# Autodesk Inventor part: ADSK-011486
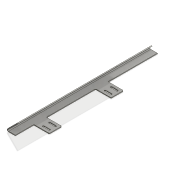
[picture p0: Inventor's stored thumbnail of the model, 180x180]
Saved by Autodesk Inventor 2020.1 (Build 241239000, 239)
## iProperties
Created: 2000-01
Part Number: ADSK-011486
Material: 1.0312 DC05
Description: FSHTPH,SS,CP,01,038,019,230,135,PLOW,END_TAB
Document SubType Name: Tôlerie
Designer: sspink
Density: 1 g/cm^3
Sheet Metal Rule: Stahlblech 1.0312 - DC05 -   3.0 mm
Appearance: Stahl
Mass: 159.325 g
Surface Area: 1118.46 cm^2
Volume: 159.325 cm^3
Flat Pattern Width: 58.4 cm
Flat Pattern Length: 15.7693 cm
Flat Pattern Area: 920.93 cm^2
Sheet Metal Width: 584,000 mm
Sheet Metal Length: 157,693 mm
Sheet Metal Area: 92092,992 mm^2
Control State: 0
Master: False
Checked Out: False
Shininess: 57.0
Length Units: 11269
Angle Units: 11279
Time Units: 11290
Mass Units: 11283
Length Display Precision: 3
Angle Display Precision: 2
Compacted: True
CUTLENGTH: 6.20 X 23.00 (143 SI)
MATERIAL DESC: SHEET,S/S, 11 GA
MATERIAL_NUMBER: A084638
G_L: 157,7x584 mm
Thickness: 3,000 mm
Dimensions: 97,3x50x584 mm
Mass: 0,159 kg
Semi finished: Stahlblech 1.0312 - DC05 -   3.0 mm
DocNumber: ADSK-011486.ipt
Folder: 01 - Themengebiete\Simplification\01 - Packaging machine\
VDS_Category: 3D Komponenten
Density: 8.03
Volumn: 167.52272109722534
Area: 1115.3407113282015
PropertySet Name: Model Information
Author: sspink
Revision Number: -
Title: FSHTPH,SS,CP,01,038,019,230,135,PLOW,END_TAB
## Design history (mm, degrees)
node "Solide1"
  node "Extrusion1" dims "d2" = 406, "d3" = 0
  node "Extrusion2" dims "d7" = 406 (= d2), "d8" = 0
  node "Fillet1" dims "d9" = 3 (= BendRadius)
  node "Fillet2" dims "d10" = 6 (= BendRadius + Thickness)
  node "Extrusion3" dims "d15" = 63.5, "d16" = 0
  node "Extrusion4" dims "d23" = 50.8, "d24" = 0
  node "Fillet3" dims "d25" = 3
  node "Extrusion6" dims "d32" = 178, "d33" = 0
sketch "Sketch1"
  geometry: L1 (0, 0)-(35, 0); L2 (35, 0)-(35, 3); L3 (35, 3)-(0, 3); L4 (0, 3)-(0, 0)
  constraints: 8 end point, 2 parallel, 1 horizontal, 1 perpendicular
  dimensions: "d0" = 3 distance between parallel lines of L1 L3 (= thickness); "d1" = 35 distance between parallel lines of L2 L4
sketch "Sketch2"
  geometry: L1 (0, 0)-(0, 3) reference; L2 (0, 3)-(35, 3) reference; L3 (0, 3)-(44.901, 47.901); L4 (44.901, 47.901)-(42.78, 50.023); L5 (42.78, 50.023)-(-7.243, 0); L6 (-7.243, 0)-(0, 0)
  constraints: 8 end point, 2 parallel, 1 perpendicular
  dimensions: "d4" = 3 distance of L3.end L4.end (= thickness); "d5" = 45 deg angle of L2 L3; "d6" = 63.5 distance of L1.end L3.end
workplane "Arbeitsebene4"
workplane "Arbeitsebene5"
workplane "Arbeitsebene6"
workplane "Arbeitsebene7"
node "FlatPattern"
sketch "Sketch3"
  geometry: L1 (0, 3)-(0, 0) reference; L2 (406, 0)-(0, 0) reference; L3 (406, 0)-(406, 3) reference; L4 (406, 3)-(0, 3) reference; L5 (76, 3)-(76, 0); L6 (127, 3)-(127, 0); L7 (330, 3)-(330, 0); L8 (381, 3)-(381, 0)
  constraints: 8 end point, 8 point on line, 3 parallel, 1 perpendicular
  dimensions: "d11" = 25 distance between parallel lines of L8 L3; "d12" = 76 distance between parallel lines of L7 L3 (= d14); "d13" = 127 distance between parallel lines of L6 L1; "d14" = 76 distance between parallel lines of L5 L1
sketch "Sketch4"
  geometry: L1 (91.257, -330)-(91.257, -279) reference; L2 (91.257, -76)-(91.257, -25) reference; L3 (53.757, -292)-(78.757, -292); L4 (53.757, -295)-(78.757, -295); L5 (78.757, -289)-(53.757, -289); L6 (78.757, -314)-(53.757, -314); L7 (53.757, -317)-(78.757, -317); L8 (53.757, -320)-(78.757, -320); L9 (66.257, -317)-(66.257, -292); L10 (78.757, -35)-(53.757, -35); L11 (53.757, -41)-(78.757, -41); L12 (53.757, -38)-(78.757, -38); L13 (78.757, -60)-(53.757, -60); L14 (53.757, -63)-(78.757, -63); L15 (53.757, -66)-(78.757, -66); L16 (66.257, -63)-(66.257, -38); A1 r 3 centre (53.757, -292) between (53.757, -289) and (53.757, -295); A2 r 3 centre (78.757, -292) between (78.757, -295) and (78.757, -289); A3 r 3 centre (53.757, -317) between (53.757, -314) and (53.757, -320); A4 r 3 centre (78.757, -317) between (78.757, -320) and (78.757, -314); A5 r 3 centre (78.757, -38) between (78.757, -41) and (78.757, -35); A6 r 3 centre (53.757, -38) between (53.757, -35) and (53.757, -41); A7 r 3 centre (53.757, -63) between (53.757, -60) and (53.757, -66); A8 r 3 centre (78.757, -63) between (78.757, -66) and (78.757, -60); 4 further points
  constraints: 36 end point, 16 point on circle, 16 tangent, 8 centre point, 8 midpoint, 4 horizontal, 4 parallel, 2 horizontal alignment, 2 vertical
  dimensions: "d35" = 25 distance of L3.start L3.end; "d36" = 6 distance between parallel lines of L4 L5; "d37" = 12.5 distance from line of L1 L3.end; "d38" = 25 distance of L7.start L7.end; "d39" = 6 distance between parallel lines of L8 L6; "d40" = 25 distance of L9.start L9.end; "d41" = 25 distance of L12.start L12.end; "d42" = 6 distance between parallel lines of L11 L10; "d44" = 25 distance of L14.start L14.end; "d45" = 6 distance between parallel lines of L15 L13; "d46" = 25 distance of L16.start L16.end; "d47" = 12.5 distance from line of L2 L12.end; "d48" = 254 distance of point (66.257, -50.5) point (66.257, -304.5) (derived)
workplane "Work Plane3"
node "Corps solides"
node "Corps surfaciques"
sketch "Sketch6"
  geometry: L1 (-42.78, 50.023)-(-3, 10.243) reference; L2 (-44.901, 47.901)-(-42.78, 50.023) reference; L3 (-5.121, 8.121)-(-44.901, 47.901) reference; L4 (-35, 3)-(-7.243, 3) reference; L5 (-35, 0)-(-35, 3) reference; L6 (-7.243, 0)-(-35, 0) reference; L7 (-11.349, 18.592)-(-13.47, 16.47); A1 r 6 centre (-7.243, 6) between (-7.243, 0) and (-3, 10.243) reference; A2 r 3 centre (-7.243, 6) between (-7.243, 3) and (-5.121, 8.121) reference
  constraints: 2 end point, 2 point on line, 1 perpendicular
  dimensions: "d31" = 44.45 distance between parallel lines of L7 L2
feature "Extrusion_mise_à_plat2" dims "d0" = 3 (derived)
other parameters: "thickness" = 3 [user parameter; used in 2 equation terms], "d34" = -20.6375, "Thickness" = 3 (derived), "BendRadius" = 3 (= Thickness), "BendReliefWidth" = 3 (= Thickness), "BendReliefDepth" = 1.5 (= 0.5 x Thickness), "CornerReliefSize" = 12 (= 4 x Thickness), "SeamGap" = 0.00508, "MinimumRemnant" = 6 (= 2 x Thickness), "TransitionRadius" = 3 (= BendRadius), "TailleRayonJacobi" = 3 (= BendRadius), "TailleJeu" = 3 (= Thickness)
